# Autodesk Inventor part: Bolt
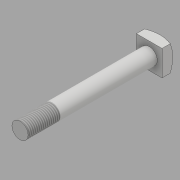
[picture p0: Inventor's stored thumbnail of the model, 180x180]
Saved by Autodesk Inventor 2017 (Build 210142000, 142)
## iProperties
Created: 2016-05
Part Number: Bolt
Material: Generic
Document SubType Name: Modeling
Designer: CADCIM
Density: 1 g/cm^3
Appearance: Default
Author: CADCIM
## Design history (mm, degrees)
sketch "Sketch1"
  geometry: L1 (9.5, 9.5)-(-9.5, 9.5); L2 (-9.5, 9.5)-(-9.5, -9.5); L3 (-9.5, -9.5)-(9.5, -9.5); L4 (9.5, -9.5)-(9.5, 9.5); L5 (0, 0)-(0, 14.108); L6 (0, 0)-(-17.802, 0)
  constraints: 12 end point, 2 horizontal, 2 parallel, 2 perpendicular, 1 vertical, 2 other
  dimensions: "d0" = 19 distance of L3.end L1.start
extrude "Extrusion1" new body sketch "Sketch1" distance "d1" = 8; taper "d2" = 0 deg
sketch "Sketch3"
  geometry: L1 (9.5, 9.5)-(-9.5, 9.5) reference; C1 r 9.5 at (0, 0); 1 further point
  constraints: 1 centre point, 1 coincident, 1 tangent
extrude "Extrusion3" sketch "Sketch3" distance "d6" = 96; taper "d7" = 65 deg
sketch "Sketch4"
  geometry: C1 r 6 at (0, 0); 1 further point
  constraints: 1 centre point, 1 coincident
  dimensions: "d10" = 12 diameter of C1
extrude "Extrusion4" join sketch "Sketch4" distance "d11" = 96; taper "d12" = 0 deg
thread "Thread2" dims "d13" = 24, "d14" = 0
body "Solid1"
